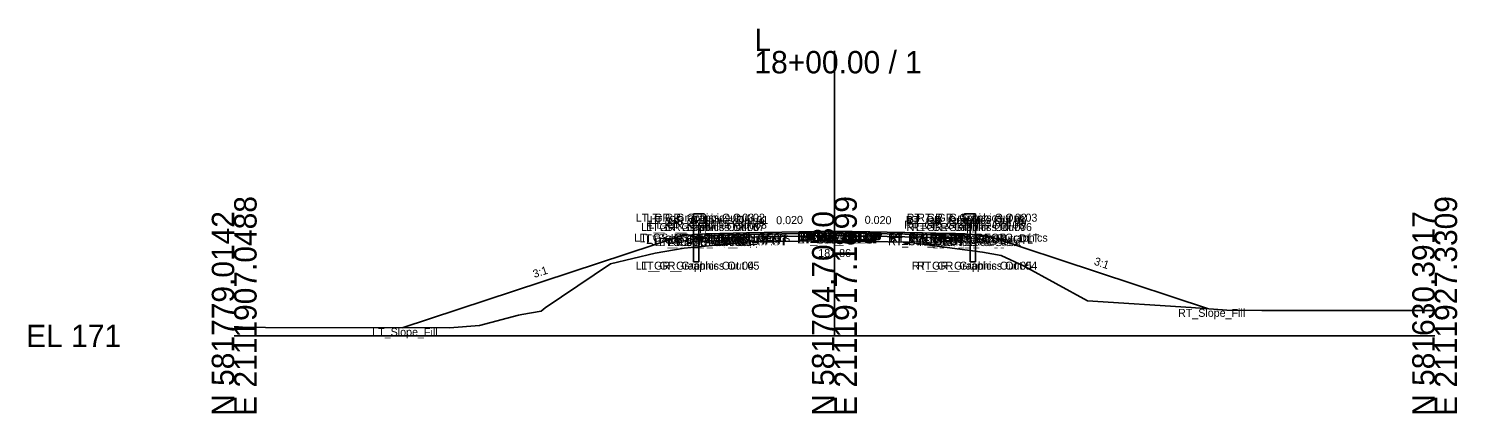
# Model space of a CAD drawing. Extents: x -26 to 3453, y -333 to 9539.
# Drawn here: x -25.7 to 152.8, y 8490.3 to 8538.4 of the extents above; entities that cross this region are included whole.
import ezdxf

# ---------------------------------------------------------------- set-up
doc = ezdxf.new("R2010")
doc.units = 0
for name, color, linetype in [('Default', 7, 'Continuous'), ('Exist Cross Section Cell', 7, 'Continuous'), ('Exist XS Center Line Elevation Label', 7, 'Continuous'), ('Exist XS Ground Line', 7, 'Continuous'), ('Prop CMT Guardrail Graphics', 7, 'Continuous'), ('Prop CMT Pvmt Course 1', 7, 'Continuous'), ('Prop CMT Pvmt Course 2', 7, 'Continuous'), ('Prop CMT Pvmt Course 3', 7, 'Continuous'), ('Prop CMT Pvmt Surface', 7, 'Continuous'), ('Prop CMT Pvmt Surface Shoulder', 7, 'Continuous'), ('Prop CMT Shld Paved Course 1', 7, 'Continuous'), ('Prop CMT Shld Paved Course 2', 7, 'Continuous'), ('Prop CMT Shld Paved Course 3', 7, 'Continuous'), ('Prop CMT Slope Grass', 7, 'Continuous'), ('Prop CMT Subgrade Earthwork', 7, 'Continuous'), ('Prop XS SE Text', 7, 'Continuous'), ('Prop XS Side Slope Text', 7, 'Continuous'), ('Scratch_Level_0', 7, 'Continuous')]:
    doc.layers.add(name, color=color, linetype=linetype)

msp = doc.modelspace()

# ---------------------------------------------------------------- linework, layer by layer
at = {"layer": 'Exist Cross Section Cell'}
for p, q in [((75, 8500), (75, 8535.62)), ((0, 8500), (75, 8500)), ((75, 8500), (150, 8500))]:
    msp.add_line(p, q, dxfattribs=at)
at = {"layer": 'Exist XS Ground Line'}
for p, q in [((52.59, 8510.33), (56.21, 8510.96)), ((56.21, 8510.96), (64.98, 8511.79)), ((64.98, 8511.79), (67, 8511.81)), ((67, 8511.81), (74.33, 8511.87)), ((74.33, 8511.87), (75, 8511.86)), ((75, 8511.86), (76.6, 8511.83)), ((76.6, 8511.83), (84.25, 8511.73)), ((84.25, 8511.73), (86.88, 8511.35)), ((86.88, 8511.35), (93.49, 8510.45)), ((38.85, 8503.49), (47, 8509.02)), ((47, 8509.02), (52.59, 8510.33)), ((93.49, 8510.45), (95.84, 8510.05)), ((95.84, 8510.05), (98.71, 8508.7)), ((98.71, 8508.7), (106.61, 8504.4)), ((106.61, 8504.4), (119.57, 8503.55)), ((119.57, 8503.55), (124.01, 8503.21)), ((30.64, 8501.31), (35.53, 8502.61)), ((35.53, 8502.61), (35.93, 8502.66)), ((35.93, 8502.66), (38.34, 8503.1)), ((38.34, 8503.1), (38.85, 8503.49)), ((124.01, 8503.21), (128.41, 8503.19)), ((128.41, 8503.19), (150, 8503.16)), ((0, 8501.13), (0.54, 8501.13)), ((0.54, 8501.13), (1.55, 8501.06)), ((1.55, 8501.06), (2.55, 8501.08)), ((2.55, 8501.08), (3.92, 8501.05)), ((3.92, 8501.05), (26.89, 8500.99)), ((26.89, 8500.99), (30.64, 8501.31))]:
    msp.add_line(p, q, dxfattribs=at)
at = {"layer": 'Prop CMT Guardrail Graphics'}
for points in [[(57.39, 8509.28), (57.39, 8515.28)], [(57.39, 8515.28), (58.72, 8515.28), (58.99, 8514.99)], [(58.99, 8514.4), (58.72, 8514.11), (58.05, 8514.11)], [(58.99, 8514.99), (58.72, 8514.7)], [(58.72, 8514.7), (58.99, 8514.4)], [(92.61, 8515.28), (91.28, 8515.28), (91.01, 8514.99)], [(91.01, 8514.99), (91.28, 8514.7)], [(91.28, 8514.7), (91.01, 8514.4)], [(91.01, 8514.4), (91.28, 8514.11), (91.95, 8514.11)], [(92.61, 8509.28), (92.61, 8515.28)], [(58.05, 8514.11), (58.05, 8509.28)], [(91.95, 8514.11), (91.95, 8509.28)], [(58.05, 8509.28), (57.39, 8509.28)], [(91.95, 8509.28), (92.61, 8509.28)]]:
    msp.add_lwpolyline(points, dxfattribs=at)
at = {"layer": 'Prop CMT Pvmt Course 1'}
for points in [[(75, 8513.1), (64, 8512.88)], [(64, 8512.67), (75, 8512.89)], [(64, 8512.88), (64, 8512.67)], [(75, 8512.89), (75, 8513.1)], [(75, 8513.1), (86, 8512.88)], [(75, 8512.89), (75, 8513.1)], [(86, 8512.67), (75, 8512.89)], [(86, 8512.88), (86, 8512.67)]]:
    msp.add_lwpolyline(points, dxfattribs=at)
msp.add_lwpolyline([(75, 8512.89), (75, 8512.97), (75, 8512.97), (75, 8512.89)], close=True, dxfattribs=at)
msp.add_lwpolyline([(75, 8512.89), (75, 8512.97), (75, 8512.97), (75, 8512.89)], close=True, dxfattribs=at)
at = {"layer": 'Prop CMT Pvmt Course 2'}
for points in [[(75, 8512.89), (64, 8512.67)], [(64, 8512.67), (64, 8512.34)], [(64, 8512.34), (75, 8512.56)], [(75, 8512.56), (75, 8512.89)], [(75, 8512.56), (75, 8512.89)], [(75, 8512.89), (86, 8512.67)], [(86, 8512.34), (75, 8512.56)], [(86, 8512.67), (86, 8512.34)]]:
    msp.add_lwpolyline(points, dxfattribs=at)
at = {"layer": 'Prop CMT Pvmt Course 3'}
for points in [[(75, 8512.56), (64, 8512.34)], [(64, 8512.34), (75, 8512.56)], [(75, 8512.56), (75, 8512.56)], [(75, 8512.56), (86, 8512.34)], [(86, 8512.34), (75, 8512.56)], [(75, 8512.56), (75, 8512.56)], [(64, 8512.34), (64, 8512.34)], [(86, 8512.34), (86, 8512.34)]]:
    msp.add_lwpolyline(points, dxfattribs=at)
at = {"layer": 'Prop CMT Pvmt Surface'}
for points in [[(75, 8513.1), (64, 8512.88)], [(75, 8513.1), (86, 8512.88)]]:
    msp.add_lwpolyline(points, dxfattribs=at)
at = {"layer": 'Prop CMT Pvmt Surface Shoulder'}
for points in [[(64, 8512.88), (59, 8512.78)], [(86, 8512.88), (91, 8512.78)]]:
    msp.add_lwpolyline(points, dxfattribs=at)
at = {"layer": 'Prop CMT Shld Paved Course 1'}
for points in [[(64, 8512.88), (59, 8512.78), (58.79, 8512.57)], [(58.79, 8512.57), (64, 8512.67)], [(64, 8512.67), (64, 8512.88)], [(86, 8512.88), (91, 8512.78), (91.21, 8512.57)], [(86, 8512.67), (86, 8512.88)], [(91.21, 8512.57), (86, 8512.67)]]:
    msp.add_lwpolyline(points, dxfattribs=at)
at = {"layer": 'Prop CMT Shld Paved Course 2'}
for points in [[(64, 8512.67), (58.79, 8512.57), (58.45, 8512.23)], [(64, 8512.34), (64, 8512.67)], [(86, 8512.67), (91.21, 8512.57), (91.55, 8512.23)], [(86, 8512.34), (86, 8512.67)], [(58.45, 8512.23), (64, 8512.34)], [(91.55, 8512.23), (86, 8512.34)]]:
    msp.add_lwpolyline(points, dxfattribs=at)
at = {"layer": 'Prop CMT Shld Paved Course 3'}
for points in [[(64, 8512.34), (58.45, 8512.23)], [(58.45, 8512.23), (64, 8512.34)], [(58.45, 8512.23), (58.45, 8512.23), (58.45, 8512.23)], [(64, 8512.34), (64, 8512.34)], [(86, 8512.34), (91.55, 8512.23)], [(91.55, 8512.23), (86, 8512.34)], [(86, 8512.34), (86, 8512.34)], [(91.55, 8512.23), (91.55, 8512.23), (91.55, 8512.23)]]:
    msp.add_lwpolyline(points, dxfattribs=at)
at = {"layer": 'Prop CMT Slope Grass'}
for points in [[(56, 8512.54), (21, 8500.99)], [(58.99, 8512.78), (56, 8512.54)], [(59, 8512.78), (58.99, 8512.78)], [(91, 8512.78), (91.01, 8512.78)], [(91.01, 8512.78), (94, 8512.54)], [(94, 8512.54), (121.75, 8503.38)]]:
    msp.add_lwpolyline(points, dxfattribs=at)
at = {"layer": 'Prop CMT Subgrade Earthwork'}
for points in [[(58.45, 8512.23), (57.98, 8512.7)], [(75, 8512.56), (64, 8512.34)], [(75, 8512.56), (86, 8512.34)], [(91.55, 8512.23), (92.02, 8512.7)], [(64, 8512.34), (58.45, 8512.23)], [(86, 8512.34), (91.55, 8512.23)]]:
    msp.add_lwpolyline(points, dxfattribs=at)

# ---------------------------------------------------------------- texts
at = {"layer": 'Default'}
msp.add_text('-', height=0.0001, dxfattribs=at).set_placement((0, 8500))
at = {"layer": 'Exist Cross Section Cell'}
for s, p in [('L', (65, 8535.62)), ('18+00.00 / 1', (65, 8532.82)), ('EL 171', (-26, 8498.6))]:
    msp.add_text(s, height=2.8, dxfattribs=at).set_placement(p)
for s, p in [('E 2111907.0488', (2.8, 8490)), ('E 2111917.1899', (77.8, 8490)), ('E 2111927.3309', (152.8, 8490)), ('N 581779.0142', (0, 8490)), ('N 581704.7030', (75, 8490)), ('N 581630.3917', (150, 8490))]:
    msp.add_text(s, height=2.8, rotation=90, dxfattribs=at).set_placement(p)
at = {"layer": 'Exist XS Center Line Elevation Label'}
msp.add_text('182.86', height=1, dxfattribs=at).set_placement((72.98, 8509.86))
at = {"layer": 'Prop XS SE Text'}
for rotation, p in [(1.1458, (67.73, 8513.95)), (358.8542, (78.77, 8514.02))]:
    msp.add_text('0.020', height=1, rotation=rotation, dxfattribs=at).set_placement(p)
at = {"layer": 'Prop XS Side Slope Text'}
for rotation, p in [(341.7371, (107.36, 8508.92)), (18.2629, (37.51, 8507.23))]:
    msp.add_text('3:1', height=1, rotation=rotation, dxfattribs=at).set_placement(p)
at = {"layer": 'Scratch_Level_0'}
for s, p in [('LT_GR_Graphics Out 03', (50.17, 8514.28)), ('LT_GR_Graphics Out 09', (51.49, 8513.7)), ('LT_GR_Graphics Out 02', (51.52, 8514.28)), ('LT_GR_Graphics Out 08', (51.76, 8513.4)), ('LT_GR_Graphics Out 01', (51.94, 8513.99)), ('RT_GR_Graphics Out 08', (83.72, 8513.4)), ('RT_GR_Graphics Out 01', (83.9, 8513.99)), ('RT_GR_Graphics Out 09', (84, 8513.7)), ('RT_GR_Graphics Out 02', (84.02, 8514.28)), ('RT_GR_Graphics Out 03', (85.34, 8514.28)), ('LT_GS_OS_GR_Face_Graphics', (49.99, 8511.78)), ('LT_Sub_Trench_Out_DLT', (50.63, 8511.7)), ('LT_GR_Graphics Out 06', (50.83, 8513.11)), ('LT_GS_OS_CTL', (51.46, 8511.54)), ('LT_GR_Graphics Out 07', (51.48, 8513.11)), ('LT_PS2_OEOP', (54.57, 8511.57)), ('LT_PS1_OEOP', (54.91, 8511.78)), ('LT_PV2_OEOT', (59.75, 8511.67)), ('LT_PV1_OEOT', (59.87, 8511.88)), ('RT_PV2_OEEOP', (70.33, 8511.89)), ('RT_PV3_OEEOP', (70.33, 8511.56)), ('RT_Sub_OEEOP', (70.36, 8511.56)), ('LT_PV2_OEEOP', (70.39, 8511.89)), ('LT_PV3_OEEOP', (70.39, 8511.56)), ('LT_Sub_OEEOP', (70.42, 8511.56)), ('RT_PV1_OEEOP', (70.45, 8511.97)), ('LT_PV1_OEEOP', (70.51, 8511.97)), ('RT_PV2_IEEOP', (70.71, 8511.89)), ('LT_PV2_IEEOP', (70.77, 8511.89)), ('RT_PV1_IEEOP', (70.83, 8511.97)), ('LT_PV1_IEEOP', (70.89, 8511.97)), ('PV2_PGL', (72.35, 8511.89)), ('PV1_PGL', (72.47, 8512.1)), ('RT_PV2_OEOT', (81.69, 8511.67)), ('RT_PV1_OEOT', (81.81, 8511.88)), ('RT_GS_OS_GR_Face_Graphics', (81.95, 8511.78)), ('RT_GR_Graphics Out 07', (83.98, 8513.11)), ('RT_Sub_Trench_Out_DLT', (84.61, 8511.7)), ('RT_GR_Graphics Out 06', (84.66, 8513.11)), ('RT_PS1_OEOP', (86.85, 8511.78)), ('RT_PS2_OEOP', (86.94, 8511.57)), ('RT_GS_OS_CTL', (89.4, 8511.54)), ('LT_Sub_Trench_Out', (52.56, 8511.23)), ('LT_PS3_Shelf_Out', (53.1, 8511.23)), ('LT_PS3_OEOP', (54.23, 8511.23)), ('LT_PV3_OEOT', (59.75, 8511.34)), ('LT_Sub_OEOT', (59.77, 8511.34)), ('RT_PV3_OEOT', (81.69, 8511.34)), ('RT_Sub_OEOT', (81.71, 8511.34)), ('RT_Sub_Trench_Out', (85.6, 8511.23)), ('RT_PS3_Shelf_Out', (86.15, 8511.23)), ('RT_PS3_OEOP', (87.28, 8511.23)), ('LT_GR_Graphics Out 04', (50.16, 8508.28)), ('LT_GR_Graphics Out 05', (50.83, 8508.28)), ('RT_GR_Graphics Out 05', (84.67, 8508.28)), ('RT_GR_Graphics Out 04', (85.32, 8508.28)), ('RT_Slope_Fill', (117.93, 8502.38)), ('LT_Slope_Fill', (17.24, 8499.99))]:
    msp.add_text(s, height=1, dxfattribs=at).set_placement(p)

doc.saveas('drawing.dxf')
